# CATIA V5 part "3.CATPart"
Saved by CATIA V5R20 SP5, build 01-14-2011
Part number: 3
Bounding box of the stored display mesh (mm): x -40 to 5, y -2.5 to 7.5, z -5 to 5
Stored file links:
  E:\IAO_2010\iao\IAO_MMS_Groupe2\IAO_MMS_Groupe2\melguidj\Catia\3.CATPart
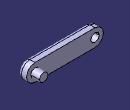
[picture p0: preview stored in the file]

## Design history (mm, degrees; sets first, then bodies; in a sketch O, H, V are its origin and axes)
Parameters
  DC3 = 35 mm
Body1 (main body)
  Sketch1 on zx-plane, origin (0, 0, 0), H (-1, 0, 0), V (0, 0, 1)
    line L1 (0, 5) -> (35, 5)
    line L2 (35, -5) -> (0, -5)
    arc A1 centre (0, 0) radius 5 from (0, 5) to (0, -5) ccw
    arc A2 centre (35, 0) radius 5 from (35, -5) to (35, 5) ccw
    point P5 (35, 0)
    point P6 (40, 0)
    distance L2 H = 5
    distance P5 V = 35 {= DC3}
    horizontal: L1 H, L2 H
    tangency: A1 L1, A1 L2, A2 L1, A2 L2
    coincidence: P5 H, A2 P6, P6 H
  Pad1: profile Sketch1, direction (0, 1, 0), length 2.5, mirrored extent
  Sketch2 on end face of Pad1, origin (0, 2.5, 0), H (-1, 0, 0), V (0, 0, 1)
    circle A1 centre (0, 0) radius 2.5
    radius A1 = 2.5
  Pad2: profile Sketch2, direction (0, 1, 0), length 5
  Sketch3 on start face of Pad1, origin (0, -2.5, 0), H (1, 0, 0), V (0, 0, 1)
    circle A1 centre (-35, 0) radius 2.5
    point P1 (-35, 0)
    reference projected arc E1 centre (-35, 0) radius 5 from (-35, 5) to (-35, -5) ccw from edge [start face of Pad1 | face of Pad1 from Sketch1.A2]
    radius A1 = 2.5
    coincidence: P1 H
    concentricity: A1 E1
  Pocket1: profile Sketch3, direction (0, 1, 0), through (limit type 6)
  Sketch4 on xy-plane, origin (0, 0, 0), H (1, 0, 0), V (0, 1, 0)
    point P1 (-35, -2.5)
    reference projected line E1 (-32.5, -2.5) -> (-37.5, -2.5) from edge [start face of Pad1 | face of Pocket1 from Sketch3.A1]
    reference projected line E2 through (-35, 0) direction (0, -1) from axis of face of Pocket1 from Sketch3.A1
    coincidence: P1 E1, E2 P1
  Fillet1: radius 2, on edge [start face of Pad1 | face of Pad1 from Sketch1.L1]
